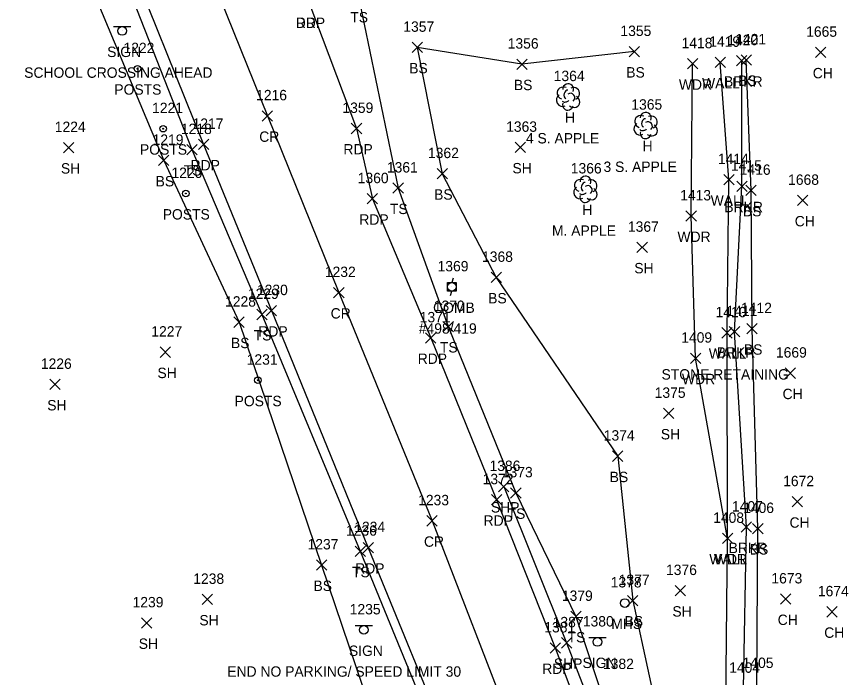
# Model space of a CAD drawing. Extents: x 1651305 to 1654558, y 539481 to 548441.
# Drawn here: x 1654203 to 1654363.2, y 544748.1 to 544875.3 of the extents above; entities that cross this region are included whole.
import ezdxf

# ---------------------------------------------------------------- set-up
doc = ezdxf.new("R2010")
doc.units = 0
for name, color, linetype in [('L_A', 7, 'Continuous'), ('L_C', 7, 'Continuous'), ('L_I', 7, 'Continuous'), ('L_TIC', 7, 'Continuous'), ('LAWA', 7, 'Continuous'), ('LAWE', 7, 'Continuous'), ('LELB', 7, 'Continuous'), ('LPST', 7, 'Continuous'), ('LTD', 7, 'Continuous'), ('LW', 7, 'Continuous'), ('P_A', 7, 'Continuous'), ('P_I', 7, 'Continuous'), ('P_TIC', 7, 'Continuous'), ('PET', 7, 'Continuous'), ('PRC', 7, 'Continuous'), ('PSP', 7, 'Continuous'), ('R_A', 7, 'Continuous'), ('R_I', 7, 'Continuous'), ('S_A', 7, 'Continuous'), ('S_C', 7, 'Continuous'), ('S_I', 7, 'Continuous'), ('SSGN', 7, 'Continuous'), ('U_A', 7, 'Continuous'), ('U_C', 7, 'Continuous'), ('U_I', 7, 'Continuous'), ('UP', 7, 'Continuous'), ('USMH', 7, 'Continuous')]:
    doc.layers.add(name, color=color, linetype=linetype)

msp = doc.modelspace()

# ---------------------------------------------------------------- linework, layer by layer
at = {"layer": 'L_TIC'}
for points in [[(1654279.17, 544868.38), (1654281.17, 544870.38)], [(1654281.17, 544868.38), (1654279.17, 544870.38)], [(1654320.98, 544867.57), (1654322.98, 544869.57)], [(1654322.98, 544867.57), (1654320.98, 544869.57)], [(1654356.84, 544867.42), (1654358.84, 544869.42)], [(1654358.84, 544867.42), (1654356.84, 544869.42)], [(1654342.53, 544865.97), (1654344.53, 544867.97)], [(1654344.53, 544865.97), (1654342.53, 544867.97)], [(1654299.33, 544865.14), (1654301.33, 544867.14)], [(1654301.33, 544865.14), (1654299.33, 544867.14)], [(1654332.19, 544865.22), (1654334.19, 544867.22)], [(1654334.19, 544865.22), (1654332.19, 544867.22)], [(1654337.52, 544865.49), (1654339.52, 544867.49)], [(1654339.52, 544865.49), (1654337.52, 544867.49)], [(1654341.65, 544865.8), (1654343.65, 544867.8)], [(1654343.65, 544865.8), (1654341.65, 544867.8)], [(1654212.05, 544849.08), (1654214.05, 544851.08)], [(1654214.05, 544849.08), (1654212.05, 544851.08)], [(1654235.78, 544848.69), (1654237.78, 544850.69)], [(1654237.78, 544848.69), (1654235.78, 544850.69)], [(1654299.02, 544849.12), (1654301.02, 544851.12)], [(1654301.02, 544849.12), (1654299.02, 544851.12)], [(1654230.34, 544846.61), (1654232.34, 544848.61)], [(1654232.34, 544846.61), (1654230.34, 544848.61)], [(1654283.97, 544844.05), (1654285.97, 544846.05)], [(1654285.97, 544844.05), (1654283.97, 544846.05)], [(1654339.18, 544842.91), (1654341.18, 544844.91)], [(1654341.18, 544842.91), (1654339.18, 544844.91)], [(1654275.49, 544841.28), (1654277.49, 544843.28)], [(1654277.49, 544841.28), (1654275.49, 544843.28)], [(1654341.7, 544841.64), (1654343.7, 544843.64)], [(1654343.7, 544841.64), (1654341.7, 544843.64)], [(1654343.44, 544840.84), (1654345.44, 544842.84)], [(1654345.44, 544840.84), (1654343.44, 544842.84)], [(1654353.37, 544838.91), (1654355.37, 544840.91)], [(1654355.37, 544838.91), (1654353.37, 544840.91)], [(1654331.91, 544835.91), (1654333.91, 544837.91)], [(1654333.91, 544835.91), (1654331.91, 544837.91)], [(1654322.48, 544829.87), (1654324.48, 544831.87)], [(1654324.48, 544829.87), (1654322.48, 544831.87)], [(1654294.38, 544824.08), (1654296.38, 544826.08)], [(1654296.38, 544824.08), (1654294.38, 544826.08)], [(1654249.25, 544816.94), (1654251.25, 544818.94)], [(1654251.25, 544816.94), (1654249.25, 544818.94)], [(1654244.85, 544815.46), (1654246.85, 544817.46)], [(1654246.85, 544815.46), (1654244.85, 544817.46)], [(1654285.12, 544814.62), (1654287.12, 544816.62)], [(1654287.12, 544814.62), (1654285.12, 544816.62)], [(1654338.82, 544813.41), (1654340.82, 544815.41)], [(1654340.82, 544813.41), (1654338.82, 544815.41)], [(1654340.26, 544813.62), (1654342.26, 544815.62)], [(1654342.26, 544813.62), (1654340.26, 544815.62)], [(1654343.63, 544814.2), (1654345.63, 544816.2)], [(1654345.63, 544814.2), (1654343.63, 544816.2)], [(1654230.64, 544809.69), (1654232.64, 544811.69)], [(1654232.64, 544809.69), (1654230.64, 544811.69)], [(1654332.78, 544808.52), (1654334.78, 544810.52)], [(1654334.78, 544808.52), (1654332.78, 544810.52)], [(1654351.03, 544805.64), (1654353.03, 544807.64)], [(1654353.03, 544805.64), (1654351.03, 544807.64)], [(1654209.42, 544803.47), (1654211.42, 544805.47)], [(1654211.42, 544803.47), (1654209.42, 544805.47)], [(1654327.58, 544797.89), (1654329.58, 544799.89)], [(1654329.58, 544797.89), (1654327.58, 544799.89)], [(1654317.78, 544789.66), (1654319.78, 544791.66)], [(1654319.78, 544789.66), (1654317.78, 544791.66)], [(1654298.15, 544782.59), (1654300.15, 544784.59)], [(1654300.15, 544782.59), (1654298.15, 544784.59)], [(1654352.37, 544780.88), (1654354.37, 544782.88)], [(1654354.37, 544780.88), (1654352.37, 544782.88)], [(1654342.54, 544776), (1654344.54, 544778)], [(1654344.54, 544776), (1654342.54, 544778)], [(1654344.75, 544775.72), (1654346.75, 544777.72)], [(1654346.75, 544775.72), (1654344.75, 544777.72)], [(1654338.93, 544773.82), (1654340.93, 544775.82)], [(1654340.93, 544773.82), (1654338.93, 544775.82)], [(1654338.93, 544773.82), (1654340.93, 544775.82)], [(1654340.93, 544773.82), (1654338.93, 544775.82)], [(1654268.19, 544771.35), (1654270.19, 544773.35)], [(1654270.19, 544771.35), (1654268.19, 544773.35)], [(1654260.74, 544768.7), (1654262.74, 544770.7)], [(1654262.74, 544768.7), (1654260.74, 544770.7)], [(1654329.81, 544763.77), (1654331.81, 544765.77)], [(1654331.81, 544763.77), (1654329.81, 544765.77)], [(1654238.72, 544762.07), (1654240.72, 544764.07)], [(1654240.72, 544762.07), (1654238.72, 544764.07)], [(1654320.65, 544761.86), (1654322.65, 544763.86)], [(1654322.65, 544761.86), (1654320.65, 544763.86)], [(1654350.1, 544762.15), (1654352.1, 544764.15)], [(1654352.1, 544762.15), (1654350.1, 544764.15)], [(1654309.71, 544758.79), (1654311.71, 544760.79)], [(1654311.71, 544758.79), (1654309.71, 544760.79)], [(1654359.06, 544759.68), (1654361.06, 544761.68)], [(1654361.06, 544759.68), (1654359.06, 544761.68)], [(1654227.04, 544757.55), (1654229.04, 544759.55)], [(1654229.04, 544757.55), (1654227.04, 544759.55)]]:
    msp.add_lwpolyline(points, dxfattribs=at)
at = {"layer": 'LAWA'}
msp.add_lwpolyline([(1654333.09, 544720.41), (1654339.57, 544742.79), (1654339.93, 544774.82), (1654333.78, 544809.52), (1654332.91, 544836.91), (1654333.19, 544866.22)], dxfattribs=at)
at = {"layer": 'LAWE'}
msp.add_lwpolyline([(1654242.51, 544465.97), (1654256.87, 544483.55), (1654283.12, 544539.87), (1654291.83, 544564.24), (1654301.76, 544593.78), (1654310.98, 544627.69), (1654314.7, 544654.65), (1654333.85, 544703.3), (1654340.89, 544719.25), (1654343, 544745.95), (1654343.54, 544777), (1654341.26, 544814.62), (1654342.7, 544842.64), (1654342.65, 544866.8)], dxfattribs=at)
at = {"layer": 'LELB'}
for points in [[(1654179.72, 544986.88), (1654191.76, 544959.88), (1654205.63, 544927.6), (1654216.28, 544901.81), (1654236.78, 544849.69), (1654250.25, 544817.94), (1654269.19, 544772.35), (1654285.71, 544732), (1654294.18, 544708.03), (1654311.84, 544664.34)], [(1654177.71, 544985.41), (1654186.4, 544960.29), (1654198.08, 544925.07), (1654208.78, 544901.64), (1654231.34, 544847.61), (1654245.85, 544816.46), (1654261.74, 544769.7), (1654274.87, 544730.83), (1654284.44, 544695.19), (1654297.61, 544656.98), (1654309.41, 544642.27)], [(1654268.86, 544879.18), (1654276.49, 544842.28), (1654286.12, 544815.62), (1654299.15, 544783.59), (1654310.71, 544759.79), (1654316.89, 544741.3), (1654328.16, 544712.61)], [(1654321.98, 544868.57), (1654300.33, 544866.14), (1654280.17, 544869.38), (1654284.97, 544845.05), (1654295.38, 544825.08), (1654318.78, 544790.66), (1654321.65, 544762.86), (1654331.12, 544719.34)], [(1654243.66, 544463.61), (1654257.64, 544478.05), (1654284.35, 544538.42), (1654294.46, 544561.39), (1654312.81, 544626.03), (1654318.85, 544643.27), (1654339.17, 544696.64), (1654344.53, 544715.65), (1654345.59, 544746.87), (1654345.75, 544776.72), (1654344.63, 544815.2), (1654344.44, 544841.84), (1654343.53, 544866.97)]]:
    msp.add_lwpolyline(points, dxfattribs=at)
at = {"layer": 'LPST'}
for centre, radius in [((1654226.29, 544865.27), 0.625), ((1654226.29, 544865.27), 0.0833), ((1654231.23, 544853.72), 0.625), ((1654231.23, 544853.72), 0.0833), ((1654235.61, 544841.23), 0.625), ((1654235.61, 544841.23), 0.0833), ((1654249.45, 544805.28), 0.625), ((1654249.45, 544805.28), 0.0833)]:
    msp.add_circle(centre, radius, dxfattribs=at)
at = {"layer": 'LTD'}
for p, q in [((1654309.18, 544859.88), (1654309.18, 544859.88)), ((1654309.18, 544859.88), (1654309.18, 544859.88)), ((1654324.13, 544854.39), (1654324.13, 544854.39)), ((1654324.13, 544854.39), (1654324.13, 544854.39)), ((1654312.52, 544842.1), (1654312.52, 544842.1)), ((1654312.52, 544842.1), (1654312.52, 544842.1))]:
    msp.add_line(p, q, dxfattribs=at)
for centre in [(1654309.23, 544861.31), (1654324.17, 544855.82), (1654312.57, 544843.53)]:
    msp.add_arc(centre, 1.05, 335.5272, 180.9563, dxfattribs=at)
for centre, major_axis, ratio, start_param, end_param in [((1654308.39, 544860.54), (1.21, -0.51), 0.895232, 1.570796, 4.712389), ((1654310.22, 544860.46), (-1.14, -0.48), 0.949671, 1.570796, 4.712389), ((1654308.1, 544859.17), (0.58, -1.04), 0.959034, 3.141593, 6.283185), ((1654308.97, 544860.34), (-0.208, -0.792), 0.645439, 3.141593, 6.283185), ((1654309.68, 544859.71), (-0.5, 0.667), 0.989748, 3.141593, 6.283185), ((1654310.18, 544859.04), (-1.09, 0.79), 0.841452, 1.570796, 4.712389), ((1654309.18, 544858.38), (0.26, 1.06), 0.942809, 1.570796, 4.712389), ((1654308.72, 544859.13), (-0.625, -0.083), 0.423636, 0, 3.141593), ((1654323.34, 544855.05), (1.21, -0.51), 0.895232, 1.570796, 4.712389), ((1654323.92, 544854.85), (-0.208, -0.792), 0.645439, 3.141593, 6.283185), ((1654324.63, 544854.22), (-0.5, 0.667), 0.989748, 3.141593, 6.283185), ((1654325.17, 544854.97), (-1.14, -0.48), 0.949671, 1.570796, 4.712389), ((1654323.04, 544853.68), (0.58, -1.04), 0.959034, 3.141593, 6.283185), ((1654323.67, 544853.64), (-0.625, -0.083), 0.423636, 0, 3.141593), ((1654325.13, 544853.55), (-1.09, 0.79), 0.841452, 1.570796, 4.712389), ((1654324.13, 544852.89), (0.26, 1.06), 0.942809, 1.570796, 4.712389), ((1654311.73, 544842.76), (1.21, -0.51), 0.895232, 1.570796, 4.712389), ((1654313.56, 544842.68), (-1.14, -0.48), 0.949671, 1.570796, 4.712389), ((1654311.44, 544841.39), (0.58, -1.04), 0.959034, 3.141593, 6.283185), ((1654312.31, 544842.55), (-0.208, -0.792), 0.645439, 3.141593, 6.283185), ((1654313.02, 544841.93), (-0.5, 0.667), 0.989748, 3.141593, 6.283185), ((1654312.52, 544840.6), (0.26, 1.06), 0.942809, 1.570796, 4.712389), ((1654312.06, 544841.35), (-0.625, -0.083), 0.423636, 0, 3.141593), ((1654313.52, 544841.26), (-1.09, 0.79), 0.841452, 1.570796, 4.712389)]:
    msp.add_ellipse(centre, major_axis=major_axis, ratio=ratio, start_param=start_param, end_param=end_param, dxfattribs=at)
at = {"layer": 'LW'}
msp.add_lwpolyline([(1654339.93, 544774.82), (1654339.82, 544814.41), (1654340.18, 544843.91), (1654338.52, 544866.49)], dxfattribs=at)
at = {"layer": 'P_TIC'}
for points in [[(1654250.31, 544855.19), (1654252.31, 544857.19)], [(1654252.31, 544855.19), (1654250.31, 544857.19)], [(1654267.46, 544852.76), (1654269.46, 544854.76)], [(1654269.46, 544852.76), (1654267.46, 544854.76)], [(1654238.03, 544849.69), (1654240.03, 544851.69)], [(1654240.03, 544849.69), (1654238.03, 544851.69)], [(1654270.52, 544839.23), (1654272.52, 544841.23)], [(1654272.52, 544839.23), (1654270.52, 544841.23)], [(1654264.06, 544821.16), (1654266.06, 544823.16)], [(1654266.06, 544821.16), (1654264.06, 544823.16)], [(1654251.07, 544817.68), (1654253.07, 544819.68)], [(1654253.07, 544817.68), (1654251.07, 544819.68)], [(1654281.76, 544812.43), (1654283.76, 544814.43)], [(1654283.76, 544812.43), (1654281.76, 544814.43)], [(1654295.83, 544783.81), (1654297.83, 544785.81)], [(1654297.83, 544783.81), (1654295.83, 544785.81)], [(1654294.45, 544781.26), (1654296.45, 544783.26)], [(1654296.45, 544781.26), (1654294.45, 544783.26)], [(1654282.02, 544777.21), (1654284.02, 544779.21)], [(1654284.02, 544777.21), (1654282.02, 544779.21)], [(1654269.72, 544772.03), (1654271.72, 544774.03)], [(1654271.72, 544772.03), (1654269.72, 544774.03)], [(1654307.93, 544753.71), (1654309.93, 544755.71)], [(1654309.93, 544753.71), (1654307.93, 544755.71)], [(1654305.75, 544752.72), (1654307.75, 544754.72)], [(1654307.75, 544752.72), (1654305.75, 544754.72)]]:
    msp.add_lwpolyline(points, dxfattribs=at)
at = {"layer": 'PET'}
for points in [[(1654139.13, 545176.5), (1654150.39, 545147.19), (1654157.16, 545131.71), (1654170.76, 545099.13), (1654178.15, 545080.65), (1654186.44, 545060.96), (1654201.83, 545022.37), (1654207.18, 545004.72), (1654219.14, 544973.24), (1654242.36, 544920.07), (1654247.53, 544907.58), (1654259.28, 544878.11), (1654268.46, 544853.76), (1654271.52, 544840.23), (1654282.76, 544813.43), (1654295.45, 544782.26), (1654306.75, 544753.72), (1654320.35, 544717.46), (1654325.71, 544702.64)], [(1654112.87, 545166.54), (1654122.04, 545140.21), (1654132.62, 545111.94), (1654135.36, 545108.19), (1654138.44, 545103.48), (1654151.39, 545069.68), (1654150.58, 545065.43), (1654160.56, 545041.12), (1654174.1, 545006.91), (1654181.29, 544989.93), (1654184.89, 544987.01), (1654195.03, 544961.54), (1654207.76, 544928.16), (1654222.99, 544890.41), (1654239.03, 544850.69), (1654252.07, 544818.68), (1654270.72, 544773.03), (1654287.36, 544732.43), (1654297.76, 544708.46), (1654313.88, 544667.1), (1654319.77, 544684.6), (1654325.71, 544702.64)]]:
    msp.add_lwpolyline(points, dxfattribs=at)
at = {"layer": 'PRC'}
msp.add_lwpolyline([(1654126.32, 545171.74), (1654141.33, 545133.41), (1654151.93, 545107.49), (1654165.21, 545072.69), (1654175.57, 545046.61), (1654188.97, 545011.94), (1654198.02, 544989.46), (1654207.45, 544965.61), (1654220.75, 544933.07), (1654235.66, 544895.02), (1654251.31, 544856.19), (1654265.06, 544822.16), (1654283.02, 544778.21), (1654298.76, 544737.49), (1654308.6, 544712.81), (1654319.77, 544684.6)], dxfattribs=at)
at = {"layer": 'PSP'}
msp.add_lwpolyline([(1654296.83, 544784.81), (1654308.93, 544754.71), (1654316.68, 544734.63), (1654322.93, 544719.55), (1654325.42, 544714.06)], dxfattribs=at)
at = {"layer": 'SSGN'}
for p, q in [((1654221.67, 544873.37), (1654225, 544873.37)), ((1654223.32, 544872.54), (1654223.32, 544872.54)), ((1654268.23, 544758.04), (1654271.56, 544758.04)), ((1654269.87, 544757.21), (1654269.87, 544757.21)), ((1654313.21, 544755.71), (1654316.54, 544755.71)), ((1654314.85, 544754.88), (1654314.85, 544754.88))]:
    msp.add_line(p, q, dxfattribs=at)
for centre in [(1654223.32, 544872.54), (1654269.87, 544757.21), (1654314.85, 544754.88)]:
    msp.add_circle(centre, 0.833, dxfattribs=at)
at = {"layer": 'UP'}
for p, q in [((1654287.08, 544824.92), (1654286.83, 544824.09)), ((1654285.99, 544822.42), (1654285.99, 544824.09)), ((1654285.99, 544824.09), (1654287.66, 544824.09)), ((1654286.83, 544823.25), (1654286.83, 544823.25)), ((1654287.66, 544824.09), (1654287.66, 544822.42)), ((1654287.66, 544822.42), (1654285.99, 544822.42)), ((1654286.58, 544821.59), (1654286.83, 544822.42))]:
    msp.add_line(p, q, dxfattribs=at)
msp.add_circle((1654286.83, 544823.25), 0.833, dxfattribs=at)
at = {"layer": 'USMH'}
for p, q in [((1654320.12, 544762.38), (1654320.12, 544762.38)), ((1654320.95, 544762.38), (1654320.95, 544762.38))]:
    msp.add_line(p, q, dxfattribs=at)
msp.add_circle((1654320.12, 544762.38), 0.833, dxfattribs=at)

# ---------------------------------------------------------------- texts
at = {"layer": 'L_A'}
for s, p in [('TS', (1654267.27, 544874.18)), ('BS', (1654278.61, 544864.38)), ('BS', (1654320.42, 544863.57)), ('CH', (1654356.33, 544863.42)), ('BS', (1654298.77, 544861.14)), ('WDR', (1654330.55, 544861.22)), ('WALL', (1654335.01, 544861.49)), ('BRKR', (1654339.24, 544861.8)), ('BS', (1654341.97, 544861.97)), ('POSTS', (1654221.83, 544860.27)), ('H', (1654308.61, 544854.88)), ('POSTS', (1654226.77, 544848.72)), ('H', (1654323.56, 544849.39)), ('SH', (1654211.54, 544845.08)), ('SH', (1654298.5, 544845.12)), ('TS', (1654235.19, 544844.69)), ('BS', (1654229.78, 544842.61)), ('BS', (1654283.41, 544840.05)), ('WALL', (1654336.67, 544838.91)), ('TS', (1654274.9, 544837.28)), ('H', (1654311.95, 544837.1)), ('BRKR', (1654339.3, 544837.64)), ('POSTS', (1654231.15, 544836.23)), ('BS', (1654342.88, 544836.84)), ('CH', (1654352.86, 544834.91)), ('WDR', (1654330.27, 544831.91)), ('SH', (1654321.97, 544825.87)), ('BS', (1654293.82, 544820.08)), ('TS', (1654248.66, 544812.94)), ('BS', (1654244.29, 544811.46)), ('TS', (1654284.53, 544810.62)), ('BS', (1654343.07, 544810.2)), ('WALL', (1654336.31, 544809.41)), ('BRKR', (1654337.85, 544809.62)), ('SH', (1654230.13, 544805.69)), ('WDR', (1654331.14, 544804.52)), ('POSTS', (1654244.99, 544800.28)), ('CH', (1654350.52, 544801.64)), ('SH', (1654208.91, 544799.47)), ('SH', (1654327.07, 544793.89)), ('BS', (1654317.22, 544785.66)), ('TS', (1654297.56, 544778.59)), ('CH', (1654351.86, 544776.88)), ('BRKR', (1654340.13, 544772)), ('BS', (1654344.19, 544771.72)), ('WALL', (1654336.41, 544769.82)), ('WDR', (1654337.29, 544769.82)), ('TS', (1654267.6, 544767.35)), ('BS', (1654260.18, 544764.7)), ('SH', (1654329.3, 544759.77)), ('SH', (1654238.21, 544758.07)), ('BS', (1654320.09, 544757.86)), ('CH', (1654349.58, 544758.15)), ('CH', (1654358.54, 544755.68)), ('TS', (1654309.12, 544754.79)), ('SH', (1654226.53, 544753.55))]:
    msp.add_text(s, height=2, dxfattribs=at).set_placement(p)
at = {"layer": 'L_C'}
for s, p in [('4 S. APPLE', (1654301.09, 544850.88)), ('3 S. APPLE', (1654316.03, 544845.39)), ('M. APPLE', (1654306.1, 544833.1)), ('STONE RETAINING', (1654327.21, 544805.41))]:
    msp.add_text(s, height=2, dxfattribs=at).set_placement(p)
at = {"layer": 'L_I'}
for s, p in [('1357', (1654277.48, 544872.38)), ('1355', (1654319.29, 544871.57)), ('1665', (1654355.06, 544871.42)), ('1356', (1654297.58, 544869.14)), ('1418', (1654331.06, 544869.22)), ('1419', (1654336.39, 544869.49)), ('1420', (1654339.87, 544869.8)), ('1421', (1654341.4, 544869.97)), ('1222', (1654223.59, 544868.27)), ('1364', (1654306.44, 544862.88)), ('1221', (1654229.1, 544856.72)), ('1365', (1654321.39, 544857.39)), ('1224', (1654210.36, 544853.08)), ('1363', (1654297.28, 544853.12)), ('1218', (1654234.65, 544852.69)), ('1219', (1654229.2, 544850.61)), ('1362', (1654282.23, 544848.05)), ('1414', (1654338.06, 544846.91)), ('1361', (1654274.32, 544845.28)), ('1366', (1654309.73, 544845.1)), ('1415', (1654340.58, 544845.64)), ('1220', (1654232.83, 544844.23)), ('1416', (1654342.26, 544844.84)), ('1668', (1654351.58, 544842.91)), ('1413', (1654330.79, 544839.91)), ('1367', (1654320.74, 544833.87)), ('1368', (1654292.64, 544828.08)), ('1229', (1654247.55, 544820.94)), ('1228', (1654243.15, 544819.46)), ('1370', (1654283.34, 544818.62)), ('1412', (1654342.51, 544818.2)), ('1410', (1654337.61, 544817.41)), ('1411', (1654339.7, 544817.62)), ('1227', (1654228.95, 544813.69)), ('1409', (1654331, 544812.52)), ('1231', (1654247.32, 544808.28)), ('1669', (1654349.24, 544809.64)), ('1226', (1654207.68, 544807.47)), ('1375', (1654325.89, 544801.89)), ('1374', (1654316.08, 544793.66)), ('1373', (1654296.45, 544786.59)), ('1672', (1654350.63, 544784.88)), ('1407', (1654340.77, 544780)), ('1406', (1654342.92, 544779.72)), ('1408', (1654337.15, 544777.82)), ('1408', (1654337.15, 544777.82)), ('1236', (1654266.44, 544775.35)), ('1237', (1654259.04, 544772.7)), ('1376', (1654328.07, 544767.77)), ('1238', (1654237.03, 544766.07)), ('1377', (1654318.96, 544765.86)), ('1673', (1654348.36, 544766.15)), ('1674', (1654357.32, 544763.68)), ('1379', (1654308.01, 544762.79)), ('1239', (1654225.34, 544761.55)), ('1404', (1654340.23, 544748.95)), ('1405', (1654342.82, 544749.87))]:
    msp.add_text(s, height=2, dxfattribs=at).set_placement(p)
at = {"layer": 'P_A'}
for s, p in [('RDP', (1654256.77, 544873.11)), ('CR', (1654249.74, 544851.19)), ('RDP', (1654265.94, 544848.76)), ('RDP', (1654236.52, 544845.69)), ('RDP', (1654269.01, 544835.23)), ('CR', (1654263.49, 544817.16)), ('RDP', (1654249.56, 544813.68)), ('RDP', (1654280.25, 544808.43)), ('SHP', (1654294.36, 544779.81)), ('RDP', (1654292.94, 544777.26)), ('CR', (1654281.46, 544773.21)), ('RDP', (1654268.21, 544768.03)), ('SHP', (1654306.47, 544749.71)), ('RDP', (1654304.24, 544748.72))]:
    msp.add_text(s, height=2, dxfattribs=at).set_placement(p)
at = {"layer": 'P_I'}
for s, p in [('1216', (1654249.13, 544859.19)), ('1359', (1654265.75, 544856.76)), ('1217', (1654236.9, 544853.69)), ('1360', (1654268.7, 544843.23)), ('1232', (1654262.37, 544825.16)), ('1230', (1654249.29, 544821.68)), ('1371', (1654280.64, 544816.43)), ('1386', (1654294.08, 544787.81)), ('1372', (1654292.76, 544785.26)), ('1233', (1654280.33, 544781.21)), ('1234', (1654268.03, 544776.03)), ('1387', (1654306.24, 544757.71)), ('1381', (1654304.63, 544756.72))]:
    msp.add_text(s, height=2, dxfattribs=at).set_placement(p)
at = {"layer": 'R_A'}
msp.add_text('DRP', height=2, dxfattribs=at).set_placement((1654256.77, 544873.11))
at = {"layer": 'R_I'}
msp.add_text('1382', height=2, dxfattribs=at).set_placement((1654315.93, 544749.67))
at = {"layer": 'S_A'}
for p in [(1654220.45, 544867.52), (1654267.01, 544752.19), (1654311.99, 544749.86)]:
    msp.add_text('SIGN', height=2, dxfattribs=at).set_placement(p)
at = {"layer": 'S_C'}
for s, p in [('SCHOOL CROSSING AHEAD', (1654204.47, 544863.52)), ('END NO PARKING/ SPEED LIMIT 30', (1654243.58, 544748.19))]:
    msp.add_text(s, height=2, dxfattribs=at).set_placement(p)
at = {"layer": 'S_I'}
for s, p in [('1235', (1654267.16, 544760.19)), ('1380', (1654312.05, 544757.86))]:
    msp.add_text(s, height=2, dxfattribs=at).set_placement(p)
at = {"layer": 'U_A'}
for s, p in [('COMB', (1654283.21, 544818.25)), ('MHS', (1654317.53, 544757.38))]:
    msp.add_text(s, height=2, dxfattribs=at).set_placement(p)
at = {"layer": 'U_C'}
msp.add_text('#498/419', height=2, dxfattribs=at).set_placement((1654280.46, 544814.25))
at = {"layer": 'U_I'}
for s, p in [('1369', (1654284.08, 544826.25)), ('1378', (1654317.42, 544765.38))]:
    msp.add_text(s, height=2, dxfattribs=at).set_placement(p)

doc.saveas('drawing.dxf')
